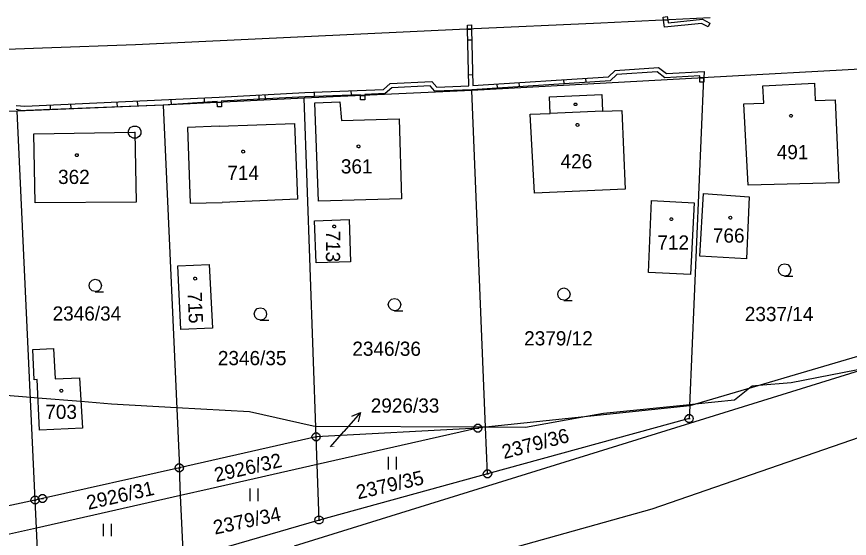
# Model space of a CAD drawing. Extents: x -760611 to -758411, y -1176479 to -1174807.
# Drawn here: x -758724.8 to -758625.1, y -1174993.7 to -1174931.2 of the extents above; entities that cross this region are included whole.
import ezdxf

# ---------------------------------------------------------------- set-up
doc = ezdxf.new("R2010")
doc.units = 0
for name, color, linetype in [('1', 7, 'Continuous'), ('11', 7, 'Continuous'), ('12', 7, 'Continuous'), ('13', 7, 'Continuous'), ('2', 7, 'Continuous'), ('3', 7, 'Continuous'), ('4', 7, 'Continuous'), ('5', 7, 'Continuous'), ('7', 7, 'Continuous'), ('8', 7, 'Continuous')]:
    doc.layers.add(name, color=color, linetype=linetype)

msp = doc.modelspace()

# ---------------------------------------------------------------- linework, layer by layer
at = {"layer": '1'}
for p, q in [((-758654.82, -1174932), (-758670.93, -1174932.75)), ((-758641.76, -1174931.39), (-758654.82, -1174932)), ((-758670.93, -1174932.75), (-758710.56, -1174934.59)), ((-758721.71, -1174934.99), (-758778.54, -1174937.47)), ((-758710.56, -1174934.59), (-758721.71, -1174934.99)), ((-758623.02, -1174937.49), (-758641.98, -1174938.52)), ((-758642.48, -1174938.55), (-758670.27, -1174940.06)), ((-758644.19, -1174977.86), (-758642.48, -1174938.55)), ((-758641.98, -1174938.52), (-758642.48, -1174938.55)), ((-758670.27, -1174940.06), (-758690.37, -1174941.01)), ((-758668.63, -1174980.42), (-758670.27, -1174940.06)), ((-758635.43, -1174939.5), (-758629.26, -1174939.21)), ((-758635.33, -1174941.58), (-758635.43, -1174939.5)), ((-758629.26, -1174939.21), (-758629.16, -1174941.29)), ((-758690.37, -1174941.01), (-758707.25, -1174941.82)), ((-758688.94, -1174981.58), (-758690.37, -1174941.01)), ((-758661, -1174940.83), (-758654.71, -1174940.56)), ((-758660.91, -1174942.83), (-758661, -1174940.83)), ((-758654.71, -1174940.56), (-758654.63, -1174942.56)), ((-758707.25, -1174941.82), (-758724.75, -1174942.54)), ((-758707.25, -1174941.82), (-758705.32, -1174985.3)), ((-758689.09, -1174941.56), (-758686.11, -1174941.45)), ((-758688.65, -1174953.33), (-758689.09, -1174941.56)), ((-758686.11, -1174941.45), (-758685.89, -1174943.67)), ((-758637.72, -1174941.69), (-758635.33, -1174941.58)), ((-758637.17, -1174951.44), (-758637.72, -1174941.69)), ((-758629.16, -1174941.29), (-758626.78, -1174941.18)), ((-758626.78, -1174941.18), (-758626.32, -1174951.13)), ((-758724.75, -1174942.54), (-758741.26, -1174943.23)), ((-758722.59, -1174989.16), (-758724.75, -1174942.54)), ((-758663.3, -1174942.93), (-758660.91, -1174942.83)), ((-758662.78, -1174952.37), (-758663.3, -1174942.93)), ((-758654.63, -1174942.56), (-758652.34, -1174942.46)), ((-758652.34, -1174942.46), (-758651.92, -1174951.89)), ((-758700.53, -1174944.37), (-758691.51, -1174944.02)), ((-758691.51, -1174944.02), (-758691.15, -1174953.09)), ((-758685.89, -1174943.67), (-758678.99, -1174943.48)), ((-758678.99, -1174943.48), (-758678.72, -1174953.05)), ((-758722.74, -1174945.27), (-758710.66, -1174945.06)), ((-758710.66, -1174945.06), (-758710.51, -1174953.44)), ((-758700.53, -1174944.37), (-758704.36, -1174944.52)), ((-758704.36, -1174944.52), (-758704.01, -1174953.58)), ((-758722.59, -1174953.55), (-758722.74, -1174945.27)), ((-758651.92, -1174951.89), (-758662.78, -1174952.37)), ((-758626.32, -1174951.13), (-758637.17, -1174951.44)), ((-758691.15, -1174953.09), (-758700.17, -1174953.49)), ((-758678.72, -1174953.05), (-758688.65, -1174953.33)), ((-758642.97, -1174959.93), (-758642.52, -1174952.42)), ((-758642.52, -1174952.42), (-758637.05, -1174952.83)), ((-758637.05, -1174952.83), (-758637.38, -1174960.24)), ((-758710.51, -1174953.44), (-758722.59, -1174953.55)), ((-758704.01, -1174953.58), (-758700.17, -1174953.49)), ((-758649.12, -1174961.87), (-758648.78, -1174953.26)), ((-758648.78, -1174953.26), (-758643.65, -1174953.54)), ((-758643.65, -1174953.54), (-758644.09, -1174962.12)), ((-758689.12, -1174955.68), (-758684.98, -1174955.55)), ((-758688.94, -1174960.73), (-758689.12, -1174955.68)), ((-758684.98, -1174955.55), (-758684.83, -1174960.6)), ((-758637.38, -1174960.24), (-758642.97, -1174959.93)), ((-758705.49, -1174961.08), (-758701.73, -1174960.92)), ((-758705.15, -1174968.73), (-758705.49, -1174961.08)), ((-758701.73, -1174960.92), (-758701.35, -1174968.56)), ((-758684.83, -1174960.6), (-758688.94, -1174960.73)), ((-758644.09, -1174962.12), (-758649.12, -1174961.87)), ((-758598.85, -1174965.89), (-758691.55, -1174994.68)), ((-758701.35, -1174968.56), (-758705.15, -1174968.73)), ((-758722.88, -1174971.11), (-758720.38, -1174971)), ((-758720.38, -1174971), (-758720.21, -1174974.62)), ((-758722.71, -1174974.74), (-758722.88, -1174971.11)), ((-758595.39, -1174971.76), (-758648.73, -1174990.25)), ((-758621.85, -1174971.3), (-758644.19, -1174977.86)), ((-758722.36, -1174974.72), (-758722.71, -1174974.74)), ((-758722.08, -1174980.78), (-758722.36, -1174974.72)), ((-758720.21, -1174974.62), (-758717.26, -1174974.49)), ((-758717.26, -1174974.49), (-758716.93, -1174980.54)), ((-758644.19, -1174977.86), (-758668.63, -1174980.42)), ((-758644.19, -1174977.86), (-758644.26, -1174979.4)), ((-758644.26, -1174979.4), (-758668.4, -1174986.02)), ((-758716.93, -1174980.54), (-758722.08, -1174980.78)), ((-758669.57, -1174980.55), (-758688.94, -1174981.58)), ((-758669.57, -1174980.55), (-758688.82, -1174984.91)), ((-758668.63, -1174980.42), (-758669.57, -1174980.55)), ((-758668.4, -1174986.02), (-758668.63, -1174980.42)), ((-758688.94, -1174981.58), (-758705.32, -1174985.3)), ((-758688.82, -1174984.91), (-758688.94, -1174981.58)), ((-758688.82, -1174984.91), (-758701.64, -1174987.81)), ((-758688.59, -1174991.55), (-758688.82, -1174984.91)), ((-758705.32, -1174985.3), (-758721.71, -1174988.97)), ((-758705.17, -1174988.61), (-758705.32, -1174985.3)), ((-758668.4, -1174986.02), (-758688.59, -1174991.55)), ((-758701.64, -1174987.81), (-758705.17, -1174988.61)), ((-758721.71, -1174988.97), (-758722.59, -1174989.16)), ((-758705.17, -1174988.61), (-758722.43, -1174992.51)), ((-758704.83, -1174996.27), (-758705.17, -1174988.61)), ((-758722.59, -1174989.16), (-758739.58, -1174992.81)), ((-758722.43, -1174992.51), (-758722.59, -1174989.16)), ((-758648.73, -1174990.25), (-758683.75, -1175000)), ((-758688.59, -1174991.55), (-758704.83, -1174996.27)), ((-758722.43, -1174992.51), (-758739.46, -1174996.37)), ((-758722.03, -1175001.26), (-758722.43, -1174992.51))]:
    msp.add_line(p, q, dxfattribs=at)
at = {"layer": '11'}
msp.add_lwpolyline([(-758622.6, -1174973.27), (-758632.03, -1174975.1), (-758635.93, -1174975.43), (-758636.7, -1174975.5), (-758637.02, -1174975.75), (-758638.82, -1174977.18), (-758643.53, -1174977.67), (-758644.18, -1174977.73), (-758654.52, -1174978.8), (-758656.55, -1174979.16), (-758663.85, -1174980.44), (-758668.63, -1174980.42), (-758688.98, -1174980.32), (-758689.29, -1174980.31), (-758696.92, -1174978.58), (-758705.64, -1174978.09), (-758713.45, -1174977.66), (-758717.1, -1174977.36), (-758722.26, -1174976.94), (-758723.16, -1174976.86), (-758740.17, -1174975.47)], dxfattribs=at)
at = {"layer": '12'}
for p, q in [((-758635.43, -1174939.5), (-758629.26, -1174939.21)), ((-758635.33, -1174941.58), (-758635.43, -1174939.5)), ((-758629.26, -1174939.21), (-758629.16, -1174941.29)), ((-758689.09, -1174941.56), (-758686.11, -1174941.45)), ((-758688.65, -1174953.33), (-758689.09, -1174941.56)), ((-758686.11, -1174941.45), (-758685.89, -1174943.67)), ((-758637.72, -1174941.69), (-758635.33, -1174941.58)), ((-758637.17, -1174951.44), (-758637.72, -1174941.69)), ((-758629.16, -1174941.29), (-758626.78, -1174941.18)), ((-758626.78, -1174941.18), (-758626.32, -1174951.13)), ((-758663.3, -1174942.93), (-758660.91, -1174942.83)), ((-758662.78, -1174952.37), (-758663.3, -1174942.93)), ((-758654.63, -1174942.56), (-758660.91, -1174942.83)), ((-758654.63, -1174942.56), (-758652.34, -1174942.46)), ((-758652.34, -1174942.46), (-758651.92, -1174951.89)), ((-758700.53, -1174944.37), (-758691.51, -1174944.02)), ((-758691.51, -1174944.02), (-758691.15, -1174953.09)), ((-758685.89, -1174943.67), (-758678.99, -1174943.48)), ((-758678.99, -1174943.48), (-758678.72, -1174953.05)), ((-758722.74, -1174945.27), (-758710.66, -1174945.06)), ((-758710.66, -1174945.06), (-758710.51, -1174953.44)), ((-758700.53, -1174944.37), (-758704.36, -1174944.52)), ((-758704.36, -1174944.52), (-758704.01, -1174953.58)), ((-758722.59, -1174953.55), (-758722.74, -1174945.27)), ((-758651.92, -1174951.89), (-758662.78, -1174952.37)), ((-758626.32, -1174951.13), (-758637.17, -1174951.44)), ((-758691.15, -1174953.09), (-758700.17, -1174953.49)), ((-758678.72, -1174953.05), (-758688.65, -1174953.33)), ((-758642.97, -1174959.93), (-758642.52, -1174952.42)), ((-758642.52, -1174952.42), (-758637.05, -1174952.83)), ((-758637.05, -1174952.83), (-758637.38, -1174960.24)), ((-758710.51, -1174953.44), (-758722.59, -1174953.55)), ((-758704.01, -1174953.58), (-758700.17, -1174953.49)), ((-758649.12, -1174961.87), (-758648.78, -1174953.26)), ((-758648.78, -1174953.26), (-758643.65, -1174953.54)), ((-758643.65, -1174953.54), (-758644.09, -1174962.12)), ((-758689.12, -1174955.68), (-758684.98, -1174955.55)), ((-758688.94, -1174960.73), (-758689.12, -1174955.68)), ((-758684.98, -1174955.55), (-758684.83, -1174960.6)), ((-758637.38, -1174960.24), (-758642.97, -1174959.93)), ((-758705.49, -1174961.08), (-758701.73, -1174960.92)), ((-758705.15, -1174968.73), (-758705.49, -1174961.08)), ((-758701.73, -1174960.92), (-758701.35, -1174968.56)), ((-758684.83, -1174960.6), (-758688.94, -1174960.73)), ((-758644.09, -1174962.12), (-758649.12, -1174961.87)), ((-758701.35, -1174968.56), (-758705.15, -1174968.73)), ((-758722.88, -1174971.11), (-758720.38, -1174971)), ((-758720.38, -1174971), (-758720.21, -1174974.62)), ((-758722.71, -1174974.74), (-758722.88, -1174971.11)), ((-758722.36, -1174974.72), (-758722.71, -1174974.74)), ((-758722.08, -1174980.78), (-758722.36, -1174974.72)), ((-758720.21, -1174974.62), (-758717.26, -1174974.49)), ((-758717.26, -1174974.49), (-758716.93, -1174980.54)), ((-758716.93, -1174980.54), (-758722.08, -1174980.78))]:
    msp.add_line(p, q, dxfattribs=at)
at = {"layer": '13'}
for p, q in [((-758647.33, -1174931.65), (-758646.83, -1174931.63)), ((-758647.2, -1174932.51), (-758647.33, -1174931.65)), ((-758642.76, -1174932.07), (-758647.2, -1174932.51)), ((-758646.83, -1174931.63), (-758646.78, -1174931.97)), ((-758646.78, -1174931.97), (-758642.66, -1174931.55)), ((-758641.99, -1174932.45), (-758642.76, -1174932.07)), ((-758642.66, -1174931.55), (-758641.77, -1174932)), ((-758641.77, -1174932), (-758641.99, -1174932.45)), ((-758670.81, -1174932.74), (-758670.82, -1174932.25)), ((-758670.81, -1174932.74), (-758670.31, -1174932.72)), ((-758670.65, -1174939.5), (-758670.81, -1174932.74)), ((-758670.31, -1174932.72), (-758670.15, -1174939.47)), ((-758670.78, -1174934.002), (-758670.28, -1174933.99)), ((-758653.93, -1174938.43), (-758653.1, -1174937.69)), ((-758653.1, -1174937.69), (-758647.92, -1174937.33)), ((-758648.08, -1174937.85), (-758652.9, -1174938.17)), ((-758647.15, -1174938.55), (-758648.08, -1174937.85)), ((-758647.92, -1174937.33), (-758646.99, -1174938.05)), ((-758646.99, -1174938.05), (-758642.45, -1174937.81)), ((-758642.45, -1174937.81), (-758642.48, -1174938.55)), ((-758680.06, -1174939.25), (-758675.07, -1174939)), ((-758675.07, -1174939), (-758674.49, -1174939.67)), ((-758670.18, -1174938.218), (-758670.68, -1174938.23)), ((-758653.73, -1174938.91), (-758670.28, -1174939.98)), ((-758670.15, -1174939.47), (-758653.93, -1174938.43)), ((-758664.661, -1174939.118), (-758664.629, -1174939.617)), ((-758659.219, -1174939.265), (-758659.251, -1174938.766)), ((-758656.678, -1174938.606), (-758656.646, -1174939.105)), ((-758652.9, -1174938.17), (-758653.73, -1174938.91)), ((-758642.97, -1174938.33), (-758647.15, -1174938.55)), ((-758642.98, -1174939.09), (-758642.97, -1174938.57)), ((-758642.5, -1174939.09), (-758642.98, -1174939.09)), ((-758642.97, -1174938.57), (-758642.97, -1174938.33)), ((-758642.48, -1174938.55), (-758642.97, -1174938.57)), ((-758642.97, -1174938.57), (-758642.48, -1174938.55)), ((-758642.48, -1174938.55), (-758642.5, -1174939.09)), ((-758690.27, -1174940.32), (-758680.86, -1174939.94)), ((-758684.774, -1174940.098), (-758684.754, -1174940.598)), ((-758680.86, -1174939.94), (-758680.06, -1174939.25)), ((-758679.86, -1174939.75), (-758680.66, -1174940.44)), ((-758675.29, -1174939.52), (-758679.86, -1174939.75)), ((-758674.71, -1174940.17), (-758675.29, -1174939.52)), ((-758670.28, -1174939.98), (-758674.71, -1174940.17)), ((-758674.49, -1174939.67), (-758670.65, -1174939.5)), ((-758667.202, -1174939.781), (-758667.234, -1174939.282)), ((-758723.84, -1174941.95), (-758700.56, -1174940.88)), ((-758702.363, -1174940.963), (-758702.34, -1174941.462)), ((-758700.56, -1174940.88), (-758690.27, -1174940.32)), ((-758690.25, -1174940.82), (-758700.29, -1174941.37)), ((-758695.742, -1174941.121), (-758695.769, -1174940.622)), ((-758695.068, -1174940.581), (-758695.041, -1174941.08)), ((-758683.62, -1174940.58), (-758690.25, -1174940.82)), ((-758689.116, -1174940.779), (-758689.135, -1174940.279)), ((-758683.62, -1174940.69), (-758683.62, -1174940.58)), ((-758683.12, -1174940.67), (-758683.62, -1174940.69)), ((-758683.62, -1174940.69), (-758683.12, -1174940.67)), ((-758683.62, -1174941.21), (-758683.62, -1174940.69)), ((-758680.66, -1174940.44), (-758683.12, -1174940.56)), ((-758683.12, -1174940.56), (-758683.12, -1174940.67)), ((-758683.12, -1174940.67), (-758683.12, -1174941.21)), ((-758724.86, -1174941.87), (-758723.84, -1174941.95)), ((-758707.25, -1174941.82), (-758723.62, -1174942.49)), ((-758720.739, -1174942.372), (-758720.759, -1174941.872)), ((-758718.346, -1174941.697), (-758718.323, -1174942.197)), ((-758712.745, -1174942.045), (-758712.766, -1174941.545)), ((-758710.354, -1174941.33), (-758710.331, -1174941.83)), ((-758700.79, -1174941.39), (-758707.25, -1174941.82)), ((-758706.278, -1174941.755), (-758706.311, -1174941.256)), ((-758700.78, -1174941.51), (-758700.79, -1174941.39)), ((-758700.28, -1174941.49), (-758700.78, -1174941.51)), ((-758700.75, -1174942.04), (-758700.78, -1174941.51)), ((-758700.29, -1174941.37), (-758700.28, -1174941.49)), ((-758683.12, -1174941.21), (-758683.62, -1174941.21)), ((-758724.12, -1174942.51), (-758724.86, -1174942.37)), ((-758723.62, -1174942.49), (-758724.12, -1174942.51))]:
    msp.add_line(p, q, dxfattribs=at)
for points in [[(-758647.33, -1174931.65), (-758647.38, -1174931.3), (-758646.88, -1174931.23), (-758646.83, -1174931.63)], [(-758670.82, -1174932.25), (-758670.32, -1174932.23), (-758670.31, -1174932.72), (-758670.81, -1174932.74)]]:
    msp.add_lwpolyline(points, close=True, dxfattribs=at)
msp.add_lwpolyline([(-758700.78, -1174941.51), (-758700.28, -1174941.49), (-758700.26, -1174942.02), (-758700.75, -1174942.04)], dxfattribs=at)
at = {"layer": '3'}
for p, q in [((-758680.29, -1174983.98), (-758680.29, -1174985.48)), ((-758679.29, -1174985.48), (-758679.29, -1174983.98)), ((-758696.88, -1174987.77), (-758696.88, -1174989.27)), ((-758695.88, -1174989.27), (-758695.88, -1174987.77)), ((-758714.46, -1174991.99), (-758714.46, -1174993.49)), ((-758713.46, -1174993.49), (-758713.46, -1174991.99))]:
    msp.add_line(p, q, dxfattribs=at)
for points in [[(-758632.81, -1174962.31), (-758633.19, -1174962.21), (-758633.46, -1174961.94), (-758633.56, -1174961.57), (-758633.46, -1174961.2), (-758633.19, -1174960.93), (-758632.82, -1174960.83), (-758632.45, -1174960.93), (-758632.18, -1174961.2), (-758632.08, -1174961.58), (-758632.18, -1174961.96), (-758632.45, -1174962.23), (-758632.83, -1174962.33), (-758631.83, -1174962.33)], [(-758715.38, -1174964.18), (-758715.76, -1174964.08), (-758716.03, -1174963.81), (-758716.13, -1174963.44), (-758716.03, -1174963.07), (-758715.76, -1174962.8), (-758715.39, -1174962.7), (-758715.02, -1174962.8), (-758714.75, -1174963.07), (-758714.65, -1174963.45), (-758714.75, -1174963.83), (-758715.02, -1174964.1), (-758715.4, -1174964.2), (-758714.4, -1174964.2)], [(-758659.25, -1174965.22), (-758659.63, -1174965.12), (-758659.9, -1174964.85), (-758660, -1174964.48), (-758659.9, -1174964.11), (-758659.63, -1174963.84), (-758659.26, -1174963.74), (-758658.89, -1174963.84), (-758658.62, -1174964.11), (-758658.52, -1174964.49), (-758658.62, -1174964.87), (-758658.89, -1174965.14), (-758659.27, -1174965.24), (-758658.27, -1174965.24)], [(-758679.54, -1174966.47), (-758679.92, -1174966.37), (-758680.19, -1174966.1), (-758680.29, -1174965.73), (-758680.19, -1174965.36), (-758679.92, -1174965.09), (-758679.55, -1174964.99), (-758679.18, -1174965.09), (-758678.91, -1174965.36), (-758678.81, -1174965.74), (-758678.91, -1174966.12), (-758679.18, -1174966.39), (-758679.56, -1174966.49), (-758678.56, -1174966.49)], [(-758695.6, -1174967.59), (-758695.98, -1174967.49), (-758696.25, -1174967.22), (-758696.35, -1174966.85), (-758696.25, -1174966.48), (-758695.98, -1174966.21), (-758695.61, -1174966.11), (-758695.24, -1174966.21), (-758694.97, -1174966.48), (-758694.87, -1174966.86), (-758694.97, -1174967.24), (-758695.24, -1174967.51), (-758695.62, -1174967.61), (-758694.62, -1174967.61)]]:
    msp.add_lwpolyline(points, dxfattribs=at)
at = {"layer": '4'}
msp.add_line((-758654.63, -1174942.56), (-758660.91, -1174942.83), dxfattribs=at)
at = {"layer": '5'}
for points in [[(-758657.78, -1174941.58), (-758657.69, -1174941.73), (-758657.78, -1174941.88), (-758657.96, -1174941.88), (-758658.05, -1174941.73), (-758657.96, -1174941.58)], [(-758632.05, -1174942.94), (-758631.95, -1174942.96), (-758631.9, -1174943.05), (-758631.88, -1174943.11), (-758631.9, -1174943.2), (-758631.98, -1174943.27), (-758632.05, -1174943.28), (-758632.14, -1174943.25), (-758632.2, -1174943.19), (-758632.22, -1174943.11), (-758632.2, -1174943.02), (-758632.12, -1174942.95)], [(-758657.63, -1174944.04), (-758657.53, -1174944.06), (-758657.48, -1174944.15), (-758657.46, -1174944.21), (-758657.48, -1174944.3), (-758657.56, -1174944.37), (-758657.63, -1174944.38), (-758657.72, -1174944.35), (-758657.78, -1174944.29), (-758657.8, -1174944.21), (-758657.78, -1174944.12), (-758657.7, -1174944.05)], [(-758683.87, -1174946.6), (-758683.77, -1174946.62), (-758683.72, -1174946.71), (-758683.7, -1174946.77), (-758683.72, -1174946.86), (-758683.8, -1174946.93), (-758683.87, -1174946.94), (-758683.96, -1174946.91), (-758684.02, -1174946.85), (-758684.04, -1174946.77), (-758684.02, -1174946.68), (-758683.94, -1174946.61)], [(-758717.6, -1174947.66), (-758717.5, -1174947.68), (-758717.45, -1174947.77), (-758717.43, -1174947.83), (-758717.45, -1174947.92), (-758717.53, -1174947.99), (-758717.6, -1174948), (-758717.69, -1174947.97), (-758717.75, -1174947.91), (-758717.77, -1174947.83), (-758717.75, -1174947.74), (-758717.67, -1174947.67)], [(-758697.67, -1174947.23), (-758697.57, -1174947.25), (-758697.52, -1174947.34), (-758697.5, -1174947.4), (-758697.52, -1174947.49), (-758697.6, -1174947.56), (-758697.67, -1174947.57), (-758697.76, -1174947.54), (-758697.82, -1174947.48), (-758697.84, -1174947.4), (-758697.82, -1174947.31), (-758697.74, -1174947.24)], [(-758646.4, -1174955.32), (-758646.3, -1174955.34), (-758646.25, -1174955.43), (-758646.23, -1174955.49), (-758646.25, -1174955.58), (-758646.33, -1174955.65), (-758646.4, -1174955.66), (-758646.49, -1174955.63), (-758646.55, -1174955.57), (-758646.57, -1174955.49), (-758646.55, -1174955.4), (-758646.47, -1174955.33)], [(-758639.32, -1174955.15), (-758639.22, -1174955.17), (-758639.17, -1174955.26), (-758639.15, -1174955.32), (-758639.17, -1174955.41), (-758639.25, -1174955.48), (-758639.32, -1174955.49), (-758639.41, -1174955.46), (-758639.47, -1174955.4), (-758639.49, -1174955.32), (-758639.47, -1174955.23), (-758639.39, -1174955.16)], [(-758686.77, -1174956.2), (-758686.67, -1174956.22), (-758686.62, -1174956.31), (-758686.6, -1174956.37), (-758686.62, -1174956.46), (-758686.7, -1174956.53), (-758686.77, -1174956.54), (-758686.86, -1174956.51), (-758686.92, -1174956.45), (-758686.94, -1174956.37), (-758686.92, -1174956.28), (-758686.84, -1174956.21)], [(-758703.42, -1174962.45), (-758703.32, -1174962.47), (-758703.27, -1174962.56), (-758703.25, -1174962.62), (-758703.27, -1174962.71), (-758703.35, -1174962.78), (-758703.42, -1174962.79), (-758703.51, -1174962.76), (-758703.57, -1174962.7), (-758703.59, -1174962.62), (-758703.57, -1174962.53), (-758703.49, -1174962.46)], [(-758719.46, -1174975.88), (-758719.36, -1174975.9), (-758719.31, -1174975.99), (-758719.29, -1174976.05), (-758719.31, -1174976.14), (-758719.39, -1174976.21), (-758719.46, -1174976.22), (-758719.55, -1174976.19), (-758719.61, -1174976.13), (-758719.63, -1174976.05), (-758719.61, -1174975.96), (-758719.53, -1174975.89)]]:
    msp.add_lwpolyline(points, close=True, dxfattribs=at)
at = {"layer": '7'}
for p in [(-758683.63, -1174978.677), (-758687.2, -1174982.78)]:
    msp.add_line(p, (-758685.6, -1174980.94), dxfattribs=at)
msp.add_lwpolyline([(-758684.664, -1174979.103), (-758683.63, -1174978.677), (-758683.91, -1174979.76)], dxfattribs=at)
at = {"layer": '8'}
for p, q in [((-758710.71, -1174945.06), (-758710.61, -1174945.06)), ((-758644.38, -1174979.4), (-758644.14, -1174979.4)), ((-758669.69, -1174980.55), (-758669.45, -1174980.55)), ((-758689.06, -1174981.58), (-758688.82, -1174981.58)), ((-758705.44, -1174985.3), (-758705.2, -1174985.3)), ((-758668.52, -1174986.02), (-758668.28, -1174986.02)), ((-758721.83, -1174988.97), (-758721.59, -1174988.97)), ((-758722.71, -1174989.16), (-758722.47, -1174989.16)), ((-758688.71, -1174991.55), (-758688.47, -1174991.55))]:
    msp.add_line(p, q, dxfattribs=at)
for points in [[(-758710.47, -1174944.34), (-758710.13, -1174944.53), (-758709.94, -1174944.87), (-758709.94, -1174945.26), (-758710.13, -1174945.6), (-758710.47, -1174945.79), (-758710.86, -1174945.79), (-758711.2, -1174945.6), (-758711.39, -1174945.26), (-758711.39, -1174944.87), (-758711.2, -1174944.53), (-758710.86, -1174944.34)], [(-758644.11, -1174978.92), (-758643.86, -1174979.1), (-758643.76, -1174979.39), (-758643.86, -1174979.68), (-758644.11, -1174979.86), (-758644.42, -1174979.86), (-758644.67, -1174979.68), (-758644.77, -1174979.39), (-758644.67, -1174979.1), (-758644.42, -1174978.92)], [(-758669.42, -1174980.07), (-758669.17, -1174980.25), (-758669.07, -1174980.54), (-758669.17, -1174980.83), (-758669.42, -1174981.01), (-758669.73, -1174981.01), (-758669.98, -1174980.83), (-758670.08, -1174980.54), (-758669.98, -1174980.25), (-758669.73, -1174980.07)], [(-758688.79, -1174981.1), (-758688.54, -1174981.28), (-758688.44, -1174981.57), (-758688.54, -1174981.86), (-758688.79, -1174982.04), (-758689.1, -1174982.04), (-758689.35, -1174981.86), (-758689.45, -1174981.57), (-758689.35, -1174981.28), (-758689.1, -1174981.1)], [(-758705.17, -1174984.82), (-758704.92, -1174985), (-758704.82, -1174985.29), (-758704.92, -1174985.58), (-758705.17, -1174985.76), (-758705.48, -1174985.76), (-758705.73, -1174985.58), (-758705.83, -1174985.29), (-758705.73, -1174985), (-758705.48, -1174984.82)], [(-758668.25, -1174985.54), (-758668, -1174985.72), (-758667.9, -1174986.01), (-758668, -1174986.3), (-758668.25, -1174986.48), (-758668.56, -1174986.48), (-758668.81, -1174986.3), (-758668.91, -1174986.01), (-758668.81, -1174985.72), (-758668.56, -1174985.54)], [(-758722.44, -1174988.68), (-758722.19, -1174988.86), (-758722.09, -1174989.15), (-758722.19, -1174989.44), (-758722.44, -1174989.62), (-758722.75, -1174989.62), (-758723, -1174989.44), (-758723.1, -1174989.15), (-758723, -1174988.86), (-758722.75, -1174988.68)], [(-758721.56, -1174988.49), (-758721.31, -1174988.67), (-758721.21, -1174988.96), (-758721.31, -1174989.25), (-758721.56, -1174989.43), (-758721.87, -1174989.43), (-758722.12, -1174989.25), (-758722.22, -1174988.96), (-758722.12, -1174988.67), (-758721.87, -1174988.49)], [(-758688.44, -1174991.07), (-758688.19, -1174991.25), (-758688.09, -1174991.54), (-758688.19, -1174991.83), (-758688.44, -1174992.01), (-758688.75, -1174992.01), (-758689, -1174991.83), (-758689.1, -1174991.54), (-758689, -1174991.25), (-758688.75, -1174991.07)]]:
    msp.add_lwpolyline(points, close=True, dxfattribs=at)

# ---------------------------------------------------------------- texts
at = {"layer": '2'}
for s, height, p in [('491', 1.7, (-758633.766, -1174948.31)), ('426', 1.7, (-758659.658, -1174949.41)), ('714', 1.7, (-758699.576, -1174950.8)), ('361', 1.7, (-758685.973, -1174950.02)), ('362', 1.7, (-758719.845, -1174951.28)), ('766', 1.7, (-758641.414, -1174958.31)), ('712', 1.7, (-758648.06, -1174959.14)), ('2346/34', 1.7, (-758720.499, -1174967.65)), ('2337/14', 1.7, (-758637.591, -1174967.71)), ('2379/12', 1.7, (-758664.018, -1174970.62)), ('2346/36', 1.7, (-758684.599, -1174971.87)), ('2346/35', 1.7, (-758700.706, -1174972.99)), ('703', 1.7, (-758721.378, -1174979.43)), ('2926/33', 0.1, (-758687.186, -1174982.78))]:
    msp.add_text(s, height=height, dxfattribs=at).set_placement(p)
for s, rotation, p in [('713', 269.40476, (-758687.733, -1174956.847)), ('715', 272.55602, (-758704.332, -1174964.239)), ('2379/36', 14.72502, (-758666.44, -1174984.25)), ('2926/32', 13.06344, (-758700.919, -1174987.006)), ('2379/35', 13.00614, (-758683.919, -1174989.077)), ('2926/31', 12.83425, (-758716.219, -1174990.327)), ('2379/34', 12.03211, (-758701.068, -1174993.301))]:
    msp.add_text(s, height=1.7, rotation=rotation, dxfattribs=at).set_placement(p)
at = {"layer": '7'}
msp.add_text('2926/33', height=1.7, dxfattribs=at).set_placement((-758682.393, -1174978.68))

doc.saveas('drawing.dxf')
